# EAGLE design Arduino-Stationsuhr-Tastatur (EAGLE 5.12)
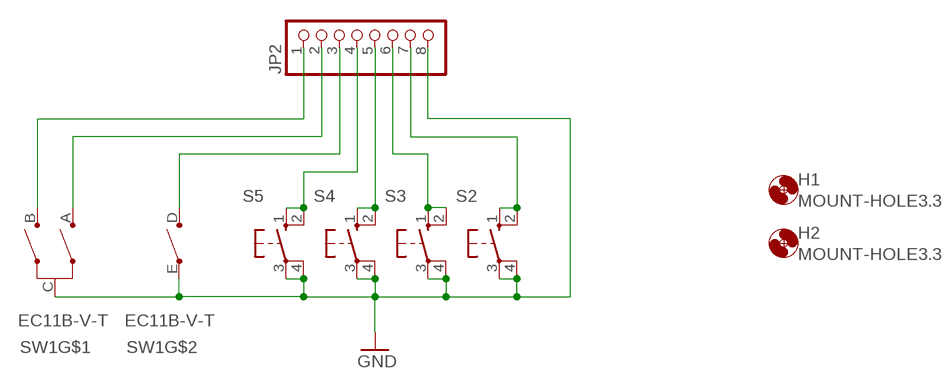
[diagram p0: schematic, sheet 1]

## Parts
H1  MOUNT-HOLE3.3  [3,3]
H2  MOUNT-HOLE3.3  [3,3]
JP2  PINHD-1X8  [1X08]
S2  10-XX  [B3F-10XX]
S3  10-XX  [B3F-10XX]
S4  10-XX  [B3F-10XX]
S5  10-XX  [B3F-10XX]
SW1  EC11B-V-T  [EC11B-V]

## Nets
GND: JP2.8 S2.3(P) S2.4(P1) S3.3(P) S3.4(P1) S4.3(P) S4.4(P1) S5.3(P) S5.4(P1) SW1.C SW1.E
N$27: JP2.3 SW1.D
N$35: JP2.4 S5.1(S) S5.2(S1)
N$37: JP2.5 S4.1(S) S4.2(S1)
N$38: JP2.6 S3.1(S) S3.2(S1)
N$39: JP2.7 S2.1(S) S2.2(S1)
N$41: JP2.1 SW1.B
N$51: JP2.2 SW1.A

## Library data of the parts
H1 H2 = holes:MOUNT-HOLE: MOUNTING HOLE with drill center marker
JP2 = pinhead:PINHD-1X8: PIN HEADER
S2-S5 = switch-omron:10-XX: OMRON SWITCH
SW1 = alps:EC11B-V-T: ALPS EC11B Vertikal mit Taster Drehimpulsgeber 11mm

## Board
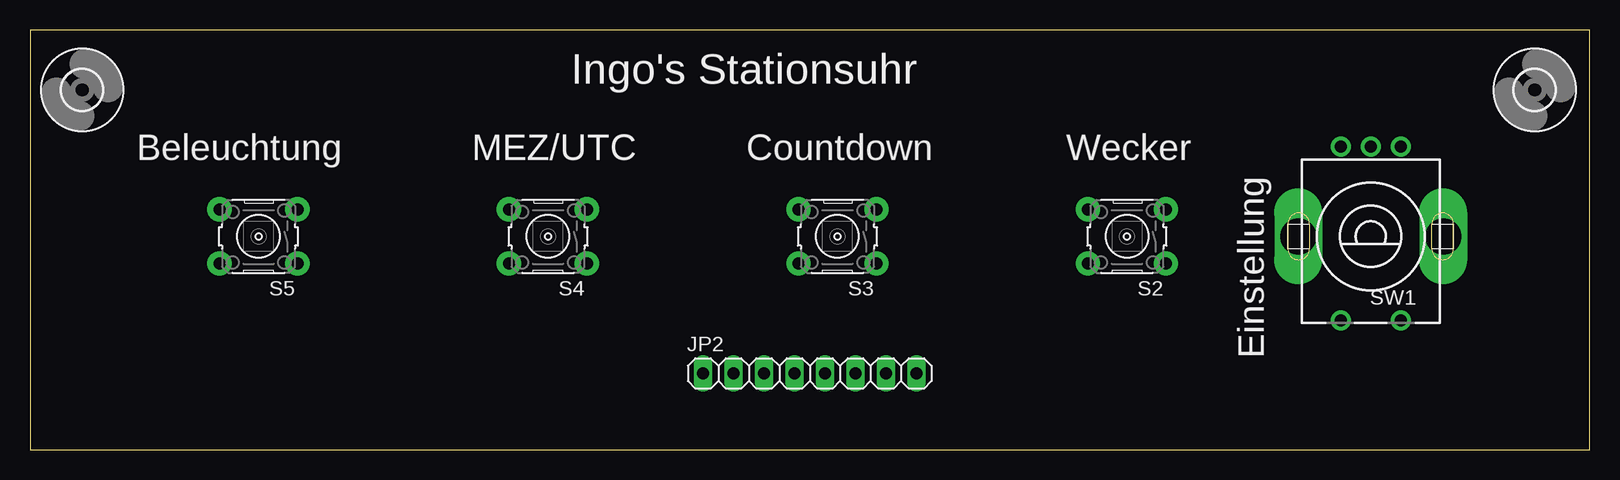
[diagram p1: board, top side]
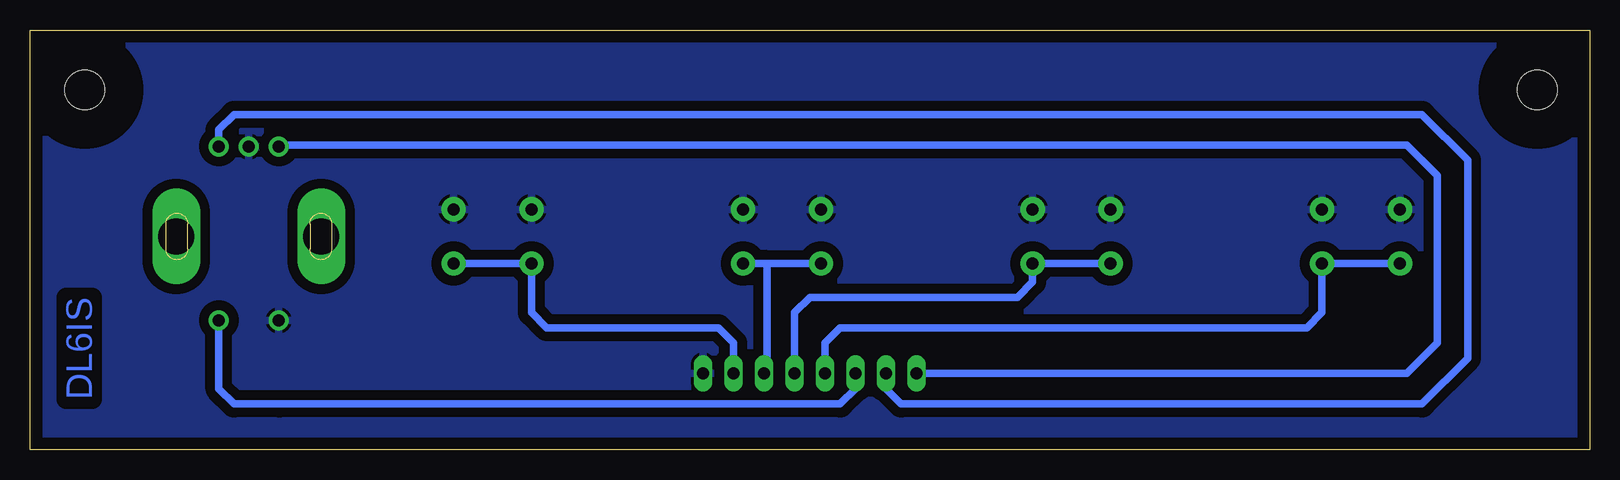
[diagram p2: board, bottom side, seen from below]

Size 130 x 35 mm. Coordinates in mm from the lower left corner, seen from the top.
Outline: 0,0 130,0 130,35 0,35 0,0
Copper layers (1*16): Top 0.035mm / dielectric 1.5mm / Bottom 0.035mm
Design rules "default": minimum track width 10mil, minimum drill 24mil, track to track 8mil, track to pad 8mil, pad to pad 8mil, via to via 8mil, smd to smd 8mil, copper to edge 40mil, drill to drill 8mil, minimum pad ring 10mil, minimum via ring 8mil, stop-mask expansion 4mil, vias tented up to drill 0mil, thermal gap 10mil

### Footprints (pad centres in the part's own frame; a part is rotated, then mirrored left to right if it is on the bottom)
3,3 = hole 3.3: 0,0
1X08 = drill 1.016 long: 1 -8.89,0; 2 -6.35,0; 3 -3.81,0; 4 -1.27,0; 5 1.27,0; 6 3.81,0; 7 6.35,0; 8 8.89,0
B3F-10XX = drill 1 pad 2.032 round: 1 -3.251,2.261; 2 3.251,2.261; 3 -3.251,-2.261; 4 3.251,-2.261
EC11B-V = drill 1 pad 1.676 round: A -2.5,-7.5; B 2.5,-7.5; C 0,-7.5; D -2.5,7; E 2.5,7 | drill 3 pad 3.3 long: G1 -6.032,0; G2 6.032,0

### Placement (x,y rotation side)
H1  4.34,30 0 top
H2  125.43,30 0 top
JP2  65,6.35 0 top
S2  91.44,17.78 180 top
S3  67.31,17.78 180 top
S4  43.18,17.78 180 top
S5  19.05,17.78 180 top
SW1  111.76,17.78 180 top

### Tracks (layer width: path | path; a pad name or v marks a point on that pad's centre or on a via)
GND
  pour Bottom (isolate 0.813): 0,35.56 130.81,35.56 130.81,0 0,0
N$27
  Bottom 0.61: JP2.3 61.19,5.08 62.46,3.81 109.22,3.81 112.99,3.81 114.26,5.08 SW1.D
N$35
  Bottom 0.61: S5.2 S5.1 22.3,11.43 23.57,10.16 29.21,10.16 62.46,10.16 63.73,8.89 JP2.4
N$37
  Bottom 0.61: S4.2 S4.1 46.43,13.97 47.7,12.7 50.8,12.7 65,12.7 66.27,11.43 JP2.5
N$38
  Bottom 0.61: 68.58,15.52 S3.2 | 68.58,15.52 S3.1 | JP2.6 68.58,6.58 68.58,15.52
N$39
  Bottom 0.61: JP2.7 71.35,8.89 72.62,10.16 81.28,10.16 86.92,10.16 88.19,11.43 S2.2 S2.1
N$41
  Bottom 0.61: SW1.B 109.26,25.4 15.24,25.4 12.7,22.86 12.7,8.89 15.24,6.35 JP2.1
N$51
  Bottom 0.61: SW1.A 114.26,26.67 112.99,27.94 13.97,27.94 10.16,24.13 10.16,7.62 13.97,3.81 57.38,3.81 58.65,5.08 JP2.2

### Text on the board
Bottom: DL6IS
tNames: Ingo's Stationsuhr | Beleuchtung | MEZ/UTC | Countdown | Wecker | Einstellung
